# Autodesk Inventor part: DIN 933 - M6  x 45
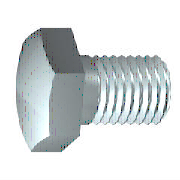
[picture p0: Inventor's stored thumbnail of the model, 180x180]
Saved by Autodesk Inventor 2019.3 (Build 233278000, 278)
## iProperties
Created: 2018-01
Part Number: DIN 933 - M6  x 45
Material: Ocel, měkká
Description: Šestihranný šroub
Document SubType Name: Modeling
Standard: DIN 933
Designer: B-hon
Standards Organization: DIN
Language: cs-CZ
Size Designation: M6  x 45
Categories: <MemberInstance><Categories><Category DisplayName="Spojovací materiál" InternalName="e4da775c-781d-43d5-af7c-5136215cf5a6" Mnemonic="FSTN"><Category DisplayName
Density: 7.85 g/cm^3
Appearance: Pololeštěná
IsCustomPart: 0
Author: B-hon
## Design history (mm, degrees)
sketch "Náčrt1"
  geometry: L1 (0, 4.35)-(0, 2.729); L2 (3, 3)-(45, 3); L3 (45, 3)-(45, 0); L4 (45, 0)-(-0.5, 0); L5 (-9.6, 0)-(54.1, 0) reference; L6 (-0.5, 0)-(-0.5, 4.35); L7 (-0.5, 4.35)-(0, 4.35); L8 (3, 3)-(2.386, 2.729); L9 (2.386, 2.729)-(0, 2.729); L10 (0, -0.87)-(0, 5.22) reference
  constraints: 16 end point, 2 collinear, 2 perpendicular, 1 parallel
  dimensions: "d0" = 45 distance between parallel lines of L3 L1 (= NLG); "d1" = 42 distance from line of L2.start L3 (= GEL); "d2" = 6 diameter of L2 L4 (= GD); "d9" = 0.5001 distance between parallel lines of L6 L1 (computed from SD); "d10" = 8.7 diameter of L7 L4 (= SD2); "d13" = 0.61355 horizontal distance of L2.start L8.end (computed from GAL); "d14" = 5.45873 diameter of L9 L4 (= BDM)
revolve "Těleso" sketch "Náčrt1" stored, may be unused: angle "d12" = 90 deg
sketch "Náčrt2"
  geometry: L1 (0, 5.774)-(5, 2.887); L2 (5, 2.887)-(5, -2.887); L3 (5, -2.887)-(0, -5.774); L4 (0, -5.774)-(-5, -2.887); L5 (-5, -2.887)-(-5, 2.887); L6 (-5, 2.887)-(0, 5.774); 2 further points
  constraints: 12 end point, 1 coincident, 1 vertical, 11 other
  dimensions: "d11" = 10 distance between parallel lines of L5 L2 (= SW)
extrude "Hlava" join sketch "Náčrt2" distance "d3" = 3.5 (= KOH - SD); taper "d4" = 0 deg
sketch "Náčrt4"
  geometry: L1 (-4, 5)-(-4, 5.774); L2 (-4, 5.774)-(-3.554, 5.774); L3 (-3.554, 5.774)-(-4, 5); L4 (-4.7, 0)-(0.2, 0) reference; L5 (-0.5, 5.774)-(-4, 5.774) reference; L6 (-4, 2.887)-(-4, 5.774) reference
  constraints: 6 end point, 2 collinear, 1 perpendicular, 1 vertical
  dimensions: "d5" = 30 deg angle of L3 L1 (= ANG1); "d19" = 10 diameter of L1.start L4 (= SW0)
revolve "Zkosení1" sketch "Náčrt4" stored, may be unused: angle "d21" = 90 deg
workplane "Work Plane1"
body "Solid1"
feature "Závit" dims "d15" = 42 (= GEL), "d16" = 0
chamfer "Zkosení2" distance "d6" = 0.61345 (= -0.5 x SPD + 0.5 x GD); stored, may be unused: second distance "d7" = 0.61355 (computed from GUL), angle "d55" = 45 deg
other parameters: "NLG" = 45 [user parameter; used in 1 equation term], "GD" = 6 (= NND) [user parameter; used in 2 equation terms], "BDM" = 5.45873 [user parameter; used in 1 equation term], "KOH" = 4 [user parameter; used in 1 equation term], "GEL" = 42 [user parameter; used in 2 equation terms], "SW" = 10 [user parameter; used in 2 equation terms], "SW0" = 10 [user parameter; used in 1 equation term], "SPD" = 4.7731 (= NND - 1.2269 x PTC) [user parameter; used in 1 equation term], "SD2" = 8.7 [user parameter; used in 1 equation term], "SD" = 0.5 [user parameter; used in 2 equation terms], "ANG1" = 30 deg [user parameter; used in 1 equation term], "GAL" = 0.61345 (= 0.61345 x PTC) [user parameter; used in 1 equation term], "GUL" = 0.61345 (= 0.61345 x PTC) [user parameter; used in 1 equation term], "d8" = 0, "RR" = 0.25 [user parameter], "d57" = 0, "d58" = 0, "GD1" = 4.7731 (= THREADDIA - 1.2269 x PTC) [user parameter], "THREADDIA" = 6 [user parameter; used in 1 equation term], "TOA" = 30 deg [user parameter], "PTC" = 1 [user parameter; used in 5 equation terms], "NND" = 6 [user parameter; used in 2 equation terms], "E0" = 11.55 (= 1.155 x SW) [user parameter]
